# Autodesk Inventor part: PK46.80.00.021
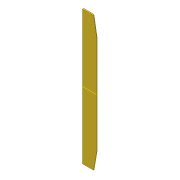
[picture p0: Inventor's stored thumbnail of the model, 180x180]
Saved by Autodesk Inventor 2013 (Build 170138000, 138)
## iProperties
Shininess: 64.0
Length Units: 11269
Angle Units: 11279
Time Units: 11290
Mass Units: 11283
Length Display Precision: 3
Angle Display Precision: 2
Compacted: True
Part Number: PK46.80.00.021
Document SubType Name: Modeling
Created: 2004-12
Designer: Salex
Manufacturer: Standard
Standards Organization: Custom
Material: Steel, Mild
Density: 7.86 g/cm^3
Mass: 136972 g
Surface Area: 15548.2 cm^2
Volume: 17426.4 cm^3
Density: 0.0
Volumn: 0.0
Area: 0.0
PropertySet Name: Model Information
Control State: 0
Master: False
Checked Out: False
Checked Out Date: 2008-10-15
Last Check In Date: 2008-10-15
Author: Salex
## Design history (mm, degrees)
sketch "Sketch1"
  geometry: L1 (280, 0)-(280, 10); L2 (280, 10)-(250, 25); L3 (0, 0)-(0, 25); L4 (0, 0)-(280, 0); L5 (0, 25)-(250, 25)
  constraints: 10 end point, 1 horizontal, 1 parallel, 1 perpendicular, 1 other
  dimensions: "d0" = 280 distance between parallel lines of L3 L1; "d2" = 10 distance of L1.start L1.end; "d16" = 30 distance from line of L2.end L1; "d17" = 25 distance of L3.start L3.end
extrude "Extrusion1" new body sketch "Sketch1" stored distance "d5" = 2650; taper "d6" = 0 deg
chamfer "Chamfer3" distance "d18" = 350; stored, may be unused: second distance "d19" = 60, angle "d26" = 45 deg
chamfer "Chamfer4" distance "d20" = 350; stored, may be unused: second distance "d21" = 60, angle "d27" = 45 deg
chamfer "Chamfer5" distance "d22" = 30; stored, may be unused: second distance "d23" = 15, angle "d28" = 45 deg
chamfer "Chamfer6" distance "d24" = 30; stored, may be unused: second distance "d25" = 15, angle "d29" = 45 deg
workplane "Work Plane1"
body "Solid1"
